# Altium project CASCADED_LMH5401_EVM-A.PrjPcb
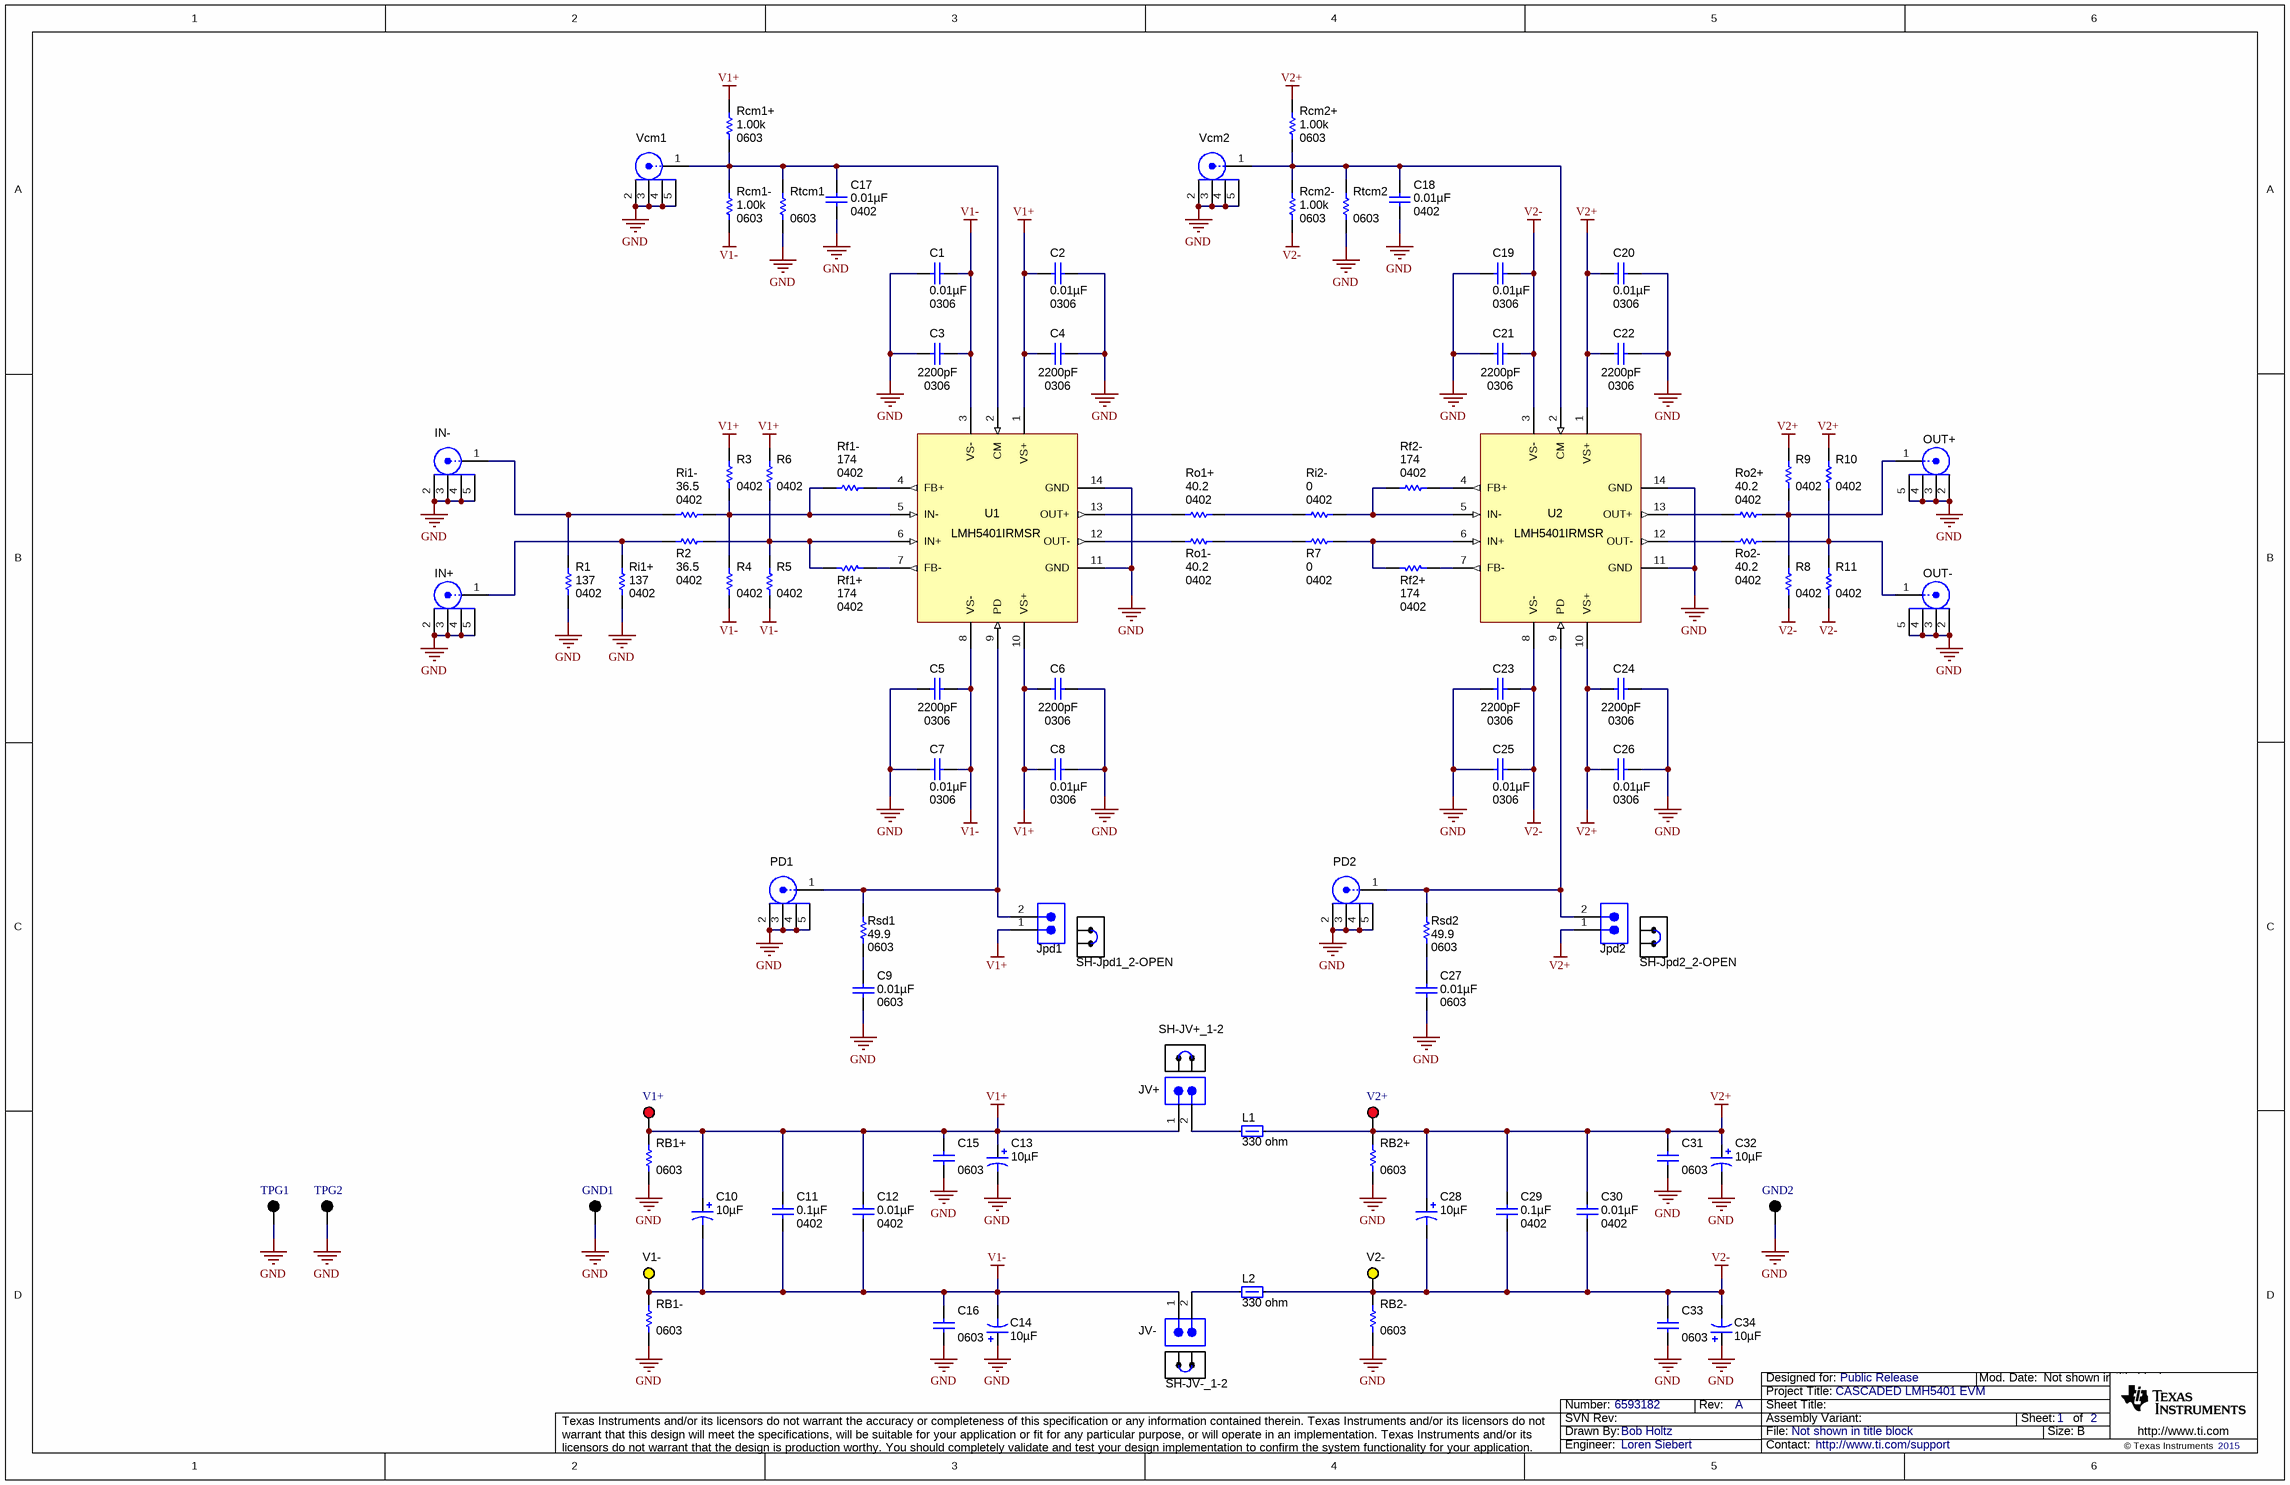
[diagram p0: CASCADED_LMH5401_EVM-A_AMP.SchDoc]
TechSupport: http://www.ti.com/support; SCH_Rev: A; PRJ_Title: CASCADED LMH5401 EVM; PRJ_Number: 6593182; PRJ_Engineer: Loren Siebert; PRJ_Customer: Public Release; PCB_Rev: A; PCB_Layout: Bob Holtz; CopyrightYear: 2015
2 sheets, 103 parts. Net scope: global (net labels, ports and power ports of the same name join across sheets).
Board file: CASCADED_LMH5401_EVM-A.PcbDoc
Sheets:
  CASCADED_LMH5401_EVM-A_AMP.SchDoc
  CASCADED_LMH5401_EVM-A_Hardware.SchDoc

## Sheet CASCADED_LMH5401_EVM-A_AMP.SchDoc
size 431 x 279 mm; Date: Not shown in title block; ApprovedBy: Not shown in title block; CheckedBy: Not shown in title block; Author: Not shown in title block; CompanyName: Not shown in title block; DrawnBy: Bob Holtz; Engineer: Not shown in title block; Organization: Not shown in title block; Address1: Not shown in title block; Address2: Not shown in title block; Address3: Not shown in title block; Address4: Not shown in title block; DocumentNumber: 1; Revision: Use project parameter SCH_Rev; SheetNumber: 1; SheetTotal: 2; PageSetup: Record=PageOptions¦CenterHorizontal=True¦CenterVertical=True¦PrintScale=0.62¦XCorrection=1.00¦YCorrection=1.00¦PrintKind=0¦BorderSize=5000000¦LeftOffset=0¦BottomOffset=0¦Orientation=2¦PaperLength=1000¦PaperWidth=1000¦Scale=100¦PaperSource=15¦PrintQuality=600¦MediaType=1¦DitherType=10¦PrintScaleMode=1¦PaperKind=Letter (8.5 x 11")¦PaperIndex=1

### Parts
C1  ValueDisplayed: 0.01µF  [0306]  (hidden comment: LLL185R71E103MA01L)
C2  ValueDisplayed: 0.01µF  [0306]  (hidden comment: LLL185R71E103MA01L)
C3  ValueDisplayed: 2200pF  [0306]  (hidden comment: LLL185R71H222MA01L)
C4  ValueDisplayed: 2200pF  [0306]  (hidden comment: LLL185R71H222MA01L)
C5  ValueDisplayed: 2200pF  [0306]  (hidden comment: LLL185R71H222MA01L)
C6  ValueDisplayed: 2200pF  [0306]  (hidden comment: LLL185R71H222MA01L)
C7  ValueDisplayed: 0.01µF  [0306]  (hidden comment: LLL185R71E103MA01L)
C8  ValueDisplayed: 0.01µF  [0306]  (hidden comment: LLL185R71E103MA01L)
C9  ValueDisplayed: 0.01µF  PackageReference: 0603  [0603L]  (hidden comment: GRM188R71C103KA01D)
C10  ValueDisplayed: 10µF  [3216-18]  (hidden comment: TPSA106K010R0900)
C11  ValueDisplayed: 0.1µF  PackageReference: 0402  [0402L]  (hidden comment: C1005X5R1A104K)
C12  ValueDisplayed: 0.01µF  PackageReference: 0402  [0402L]  (hidden comment: C1005X7R1E103K)
C13  ValueDisplayed: 10µF  [3216-18]  (hidden comment: TPSA106K010R0900)
C14  ValueDisplayed: 10µF  [3216-18]  (hidden comment: TPSA106K010R0900)
C15  PackageReference: 0603  [0603L]  (hidden comment: Used in BOM report)
C16  PackageReference: 0603  [0603L]  (hidden comment: Used in BOM report)
C17  ValueDisplayed: 0.01µF  PackageReference: 0402  [0402L]  (hidden comment: C1005X7R1E103K)
C18  ValueDisplayed: 0.01µF  PackageReference: 0402  [0402L]  (hidden comment: C1005X7R1E103K)
C19  ValueDisplayed: 0.01µF  [0306]  (hidden comment: LLL185R71E103MA01L)
C20  ValueDisplayed: 0.01µF  [0306]  (hidden comment: LLL185R71E103MA01L)
C21  ValueDisplayed: 2200pF  [0306]  (hidden comment: LLL185R71H222MA01L)
C22  ValueDisplayed: 2200pF  [0306]  (hidden comment: LLL185R71H222MA01L)
C23  ValueDisplayed: 2200pF  [0306]  (hidden comment: LLL185R71H222MA01L)
C24  ValueDisplayed: 2200pF  [0306]  (hidden comment: LLL185R71H222MA01L)
C25  ValueDisplayed: 0.01µF  [0306]  (hidden comment: LLL185R71E103MA01L)
C26  ValueDisplayed: 0.01µF  [0306]  (hidden comment: LLL185R71E103MA01L)
C27  ValueDisplayed: 0.01µF  PackageReference: 0603  [0603L]  (hidden comment: GRM188R71C103KA01D)
C28  ValueDisplayed: 10µF  [3216-18]  (hidden comment: TPSA106K010R0900)
C29  ValueDisplayed: 0.1µF  PackageReference: 0402  [0402L]  (hidden comment: C1005X5R1A104K)
C30  ValueDisplayed: 0.01µF  PackageReference: 0402  [0402L]  (hidden comment: C1005X7R1E103K)
C31  PackageReference: 0603  [0603L]  (hidden comment: Used in BOM report)
C32  ValueDisplayed: 10µF  [3216-18]  (hidden comment: TPSA106K010R0900)
C33  PackageReference: 0603  [0603L]  (hidden comment: Used in BOM report)
C34  ValueDisplayed: 10µF  [3216-18]  (hidden comment: TPSA106K010R0900)
GND1  5011  [Keystone5011]  (value not drawn)
GND2  5011  [Keystone5011]  (value not drawn)
IN+  142-0701-851  [Emerson_142-0701-851]  (value not drawn)
IN-  142-0701-851  [Emerson_142-0701-851]  (value not drawn)
Jpd1  TSW-102-07-G-S  [TSW-102-07-G-S]  (value not drawn)
Jpd2  TSW-102-07-G-S  [TSW-102-07-G-S]  (value not drawn)
JV+  TSW-102-07-G-S  [TSW-102-07-G-S]  (value not drawn)
JV-  TSW-102-07-G-S  [TSW-102-07-G-S]  (value not drawn)
L1  value 330 ohm  [0603L]  (hidden comment: BLM18SG331TN1D)
L2  value 330 ohm  [0603L]  (hidden comment: BLM18SG331TN1D)
OUT+  142-0701-851  [Emerson_142-0701-851]  (value not drawn)
OUT-  142-0701-851  [Emerson_142-0701-851]  (value not drawn)
PD1  142-0701-851  [Emerson_142-0701-851]  (value not drawn)
PD2  142-0701-851  [Emerson_142-0701-851]  (value not drawn)
R1  ValueDisplayed: 137  PackageReference: 0402  [0402L]  (hidden comment: CRCW0402137RFKED)
R2  ValueDisplayed: 36.5  PackageReference: 0402  [0402L]  (hidden comment: CRCW040236R5FKED)
R3  PackageReference: 0402  [0402L]  (hidden comment: Used in BOM report)
R4  PackageReference: 0402  [0402L]  (hidden comment: Used in BOM report)
R5  PackageReference: 0402  [0402L]  (hidden comment: Used in BOM report)
R6  PackageReference: 0402  [0402L]  (hidden comment: Used in BOM report)
R7  ValueDisplayed: 0  PackageReference: 0402  [0402L]  (hidden comment: CRCW04020000Z0ED)
R8  PackageReference: 0402  [0402L]  (hidden comment: Used in BOM report)
R9  PackageReference: 0402  [0402L]  (hidden comment: Used in BOM report)
R10  PackageReference: 0402  [0402L]  (hidden comment: Used in BOM report)
R11  PackageReference: 0402  [0402L]  (hidden comment: Used in BOM report)
RB1+  PackageReference: 0603  [0603L]  (hidden comment: Used in BOM report)
RB1-  PackageReference: 0603  [0603L]  (hidden comment: Used in BOM report)
RB2+  PackageReference: 0603  [0603L]  (hidden comment: Used in BOM report)
RB2-  PackageReference: 0603  [0603L]  (hidden comment: Used in BOM report)
Rcm1+  value 1.00k  PackageReference: 0603  [0603L]  (hidden comment: CRCW06031K00FKEA)
Rcm1-  value 1.00k  PackageReference: 0603  [0603L]  (hidden comment: CRCW06031K00FKEA)
Rcm2+  value 1.00k  PackageReference: 0603  [0603L]  (hidden comment: CRCW06031K00FKEA)
Rcm2-  value 1.00k  PackageReference: 0603  [0603L]  (hidden comment: CRCW06031K00FKEA)
Rf1+  ValueDisplayed: 174  PackageReference: 0402  [0402L]  (hidden comment: CRCW0402174RFKED)
Rf1-  ValueDisplayed: 174  PackageReference: 0402  [0402L]  (hidden comment: CRCW0402174RFKED)
Rf2+  ValueDisplayed: 174  PackageReference: 0402  [0402L]  (hidden comment: CRCW0402174RFKED)
Rf2-  ValueDisplayed: 174  PackageReference: 0402  [0402L]  (hidden comment: CRCW0402174RFKED)
Ri1+  ValueDisplayed: 137  PackageReference: 0402  [0402L]  (hidden comment: CRCW0402137RFKED)
Ri1-  ValueDisplayed: 36.5  PackageReference: 0402  [0402L]  (hidden comment: CRCW040236R5FKED)
Ri2-  ValueDisplayed: 0  PackageReference: 0402  [0402L]  (hidden comment: CRCW04020000Z0ED)
Ro1+  value 40.2  PackageReference: 0402  [0402L]  (hidden comment: CRCW040240R2FKED)
Ro1-  value 40.2  PackageReference: 0402  [0402L]  (hidden comment: CRCW040240R2FKED)
Ro2+  value 40.2  PackageReference: 0402  [0402L]  (hidden comment: CRCW040240R2FKED)
Ro2-  value 40.2  PackageReference: 0402  [0402L]  (hidden comment: CRCW040240R2FKED)
Rsd1  value 49.9  PackageReference: 0603  [0603L]  (hidden comment: CRCW060349R9FKEA)
Rsd2  value 49.9  PackageReference: 0603  [0603L]  (hidden comment: CRCW060349R9FKEA)
Rtcm1  PackageReference: 0603  [0603L]  (hidden comment: Used in BOM report)
Rtcm2  PackageReference: 0603  [0603L]  (hidden comment: Used in BOM report)
SH-Jpd1_2-OPEN  382811-6  (value not drawn)  (mechanical)
SH-Jpd2_2-OPEN  382811-6  (value not drawn)  (mechanical)
SH-JV+_1-2  382811-6  (value not drawn)  (mechanical)
SH-JV-_1-2  382811-6  (value not drawn)  (mechanical)
TPG1  5011  [Keystone5011]  (value not drawn)
TPG2  5011  [Keystone5011]  (value not drawn)
U1  LMH5401IRMSR  [RMS0014A]
U2  LMH5401IRMSR  [RMS0014A]
V1+  5010  [Keystone5010]  (value not drawn)
V1-  5014  [Keystone5014]  (value not drawn)
V2+  5010  [Keystone5010]  (value not drawn)
V2-  5014  [Keystone5014]  (value not drawn)
Vcm1  142-0701-851  [Emerson_142-0701-851]  (value not drawn)
Vcm2  142-0701-851  [Emerson_142-0701-851]  (value not drawn)

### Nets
GND: C1.1 C2.2 C3.2 C4.1 C5.2 C6.1 C7.1 C8.2 C9.2 C13.2(-) C14.1(+) C15.2 C16.2 C17.1 C18.1 C19.1 C20.2 C21.2 C22.1 C23.2 C24.1 C25.1 C26.2 C27.2 C31.2 C32.2(-) C33.2 C34.1(+) GND1.1 GND2.1 IN+.2 IN+.3 IN+.4 IN+.5 IN-.2 IN-.3 IN-.4 IN-.5 OUT+.2 OUT+.3 OUT+.4 OUT+.5 OUT-.2 OUT-.3 OUT-.4 OUT-.5 PD1.2 PD1.3 PD1.4 PD1.5 PD2.2 PD2.3 PD2.4 PD2.5 R1.1 RB1+.1 RB1-.2 RB2+.1 RB2-.2 Ri1+.1 Rtcm1.2 Rtcm2.2 TPG1.1 TPG2.1 U1.11(GND) U1.14(GND) U2.11(GND) U2.14(GND) Vcm1.2 Vcm1.3 Vcm1.4 Vcm1.5 Vcm2.2 Vcm2.3 Vcm2.4 Vcm2.5
V1+: C2.1 C4.2 C6.2 C8.1 C10.1(+) C11.2 C12.2 C13.1(+) C15.1 Jpd1.1 JV+.1 R3.2 R6.2 RB1+.2 Rcm1+.2 U1.1(VS+) U1.10(VS+) V1+.1
V1-: C1.2 C3.1 C5.1 C7.2 C10.2(-) C11.1 C12.1 C14.2(-) C16.1 JV-.1 R4.1 R5.1 RB1-.1 Rcm1-.1 U1.3(VS-) U1.8(VS-) V1-.1
V2+: C20.1 C22.2 C24.2 C26.1 C28.1(+) C29.2 C30.2 C31.1 C32.1(+) Jpd2.1 L1.2 R9.2 R10.2 RB2+.2 Rcm2+.2 U2.1(VS+) U2.10(VS+) V2+.1
V2-: C19.2 C21.1 C23.1 C25.2 C28.2(-) C29.1 C30.1 C33.1 C34.2(-) L2.2 R8.1 R11.1 RB2-.1 Rcm2-.1 U2.3(VS-) U2.8(VS-) V2-.1
NetC9_1: C9.1 Rsd1.1
NetC17_2: C17.2 Rcm1+.1 Rcm1-.2 Rtcm1.1 U1.2(CM) Vcm1.1
NetC18_2: C18.2 Rcm2+.1 Rcm2-.2 Rtcm2.1 U2.2(CM) Vcm2.1
NetC27_1: C27.1 Rsd2.1
NetIN+_1: IN+.1 R2.2 Ri1+.2
NetIN-_1: IN-.1 R1.2 Ri1-.1
NetJpd1_2: Jpd1.2 PD1.1 Rsd1.2 U1.9(PD)
NetJpd2_2: Jpd2.2 PD2.1 Rsd2.2 U2.9(PD)
NetJV+_2: JV+.2 L1.1
NetJV-_2: JV-.2 L2.1
NetOUT+_1: OUT+.1 R8.2 R9.1 Ro2+.2
NetOUT-_1: OUT-.1 R10.1 R11.2 Ro2-.2
NetR2_1: R2.1 R5.2 R6.1 Rf1+.2 U1.6(IN+)
NetR3_1: R3.1 R4.2 Rf1-.2 Ri1-.2 U1.5(IN-)
NetR7_1: R7.1 Rf2+.2 U2.6(IN+)
NetR7_2: R7.2 Ro1-.2
NetRf1+_1: Rf1+.1 U1.7(FB-)
NetRf1-_1: Rf1-.1 U1.4(FB+)
NetRf2+_1: Rf2+.1 U2.7(FB-)
NetRf2-_1: Rf2-.1 U2.4(FB+)
NetRf2-_2: Rf2-.2 Ri2-.2 U2.5(IN-)
NetRi2-_1: Ri2-.1 Ro1+.2
NetRo1+_1: Ro1+.1 U1.13(OUT+)
NetRo1-_1: Ro1-.1 U1.12(OUT-)
NetRo2+_1: Ro2+.1 U2.13(OUT+)
NetRo2-_1: Ro2-.1 U2.12(OUT-)

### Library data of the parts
C1 C2 C7 C8 C19 C20 C25 C26 = LLL185R71E103MA01L: CAP, CERM, 0.01uF, 25V, +/-20%, X7R, 0306; Manufacturer: MuRata; Polarized: N; CompType: Capacitor; U/M: EA; Cap_F: 0.00000001; Tolerance_%: 20; Value1: Unknown; VDC_V: 25; TaMin_C: -55; TaMax_C: 125
C3-C6 C21-C24 = LLL185R71H222MA01L: CAP, CERM, 2200pF, 50V, +/-20%, X7R, 0306; Manufacturer: MuRata; Polarized: N; CompType: Capacitor; U/M: EA; Cap_F: 0.0000000022; Tolerance_%: 20; Value1: Unknown; VDC_V: 50; TaMin_C: -55; TaMax_C: 125
C9 C27 = GRM188R71C103KA01D: CAP, CERM, 0.01uF, 16V, +/-10%, X7R, 0603; Manufacturer: MuRata; Polarized: N; CompType: Capacitor; U/M: EA; Cap_F: 0.00000001; Tolerance_%: 10; Value1: Unknown; VDC_V: 16; TaMin_C: -55; TaMax_C: 125
C10 C13 C14 C28 C32 C34 = TPSA106K010R0900: CAP, TA, 10uF, 10V, +/-10%, 0.9 ohm, SMD; Manufacturer: AVX; Polarized: Y; CompType: Capacitor; U/M: EA; Cap_F: 0.00001; Tolerance_%: 10; Value1: 0.9 ohm; ESR_Ohm: 0.9; IRMS_A: 0.26; TaMin_C: -55; TaMax_C: 125; Cap_Case: A
C11 C29 = C1005X5R1A104K: CAP, CERM, 0.1uF, 10V, +/-10%, X5R, 0402; Manufacturer: TDK; Polarized: N; CompType: Capacitor; U/M: EA; Cap_F: 0.0000001; Tolerance_%: 10; ESR_Ohm: 0.0186; Value1: 0.0186 ohm; TaMin_C: -55; TaMax_C: 85
C12 C17 C18 C30 = C1005X7R1E103K: CAP, CERM, 0.01uF, 25V, +/-10%, X7R, 0402; Manufacturer: TDK; ESR_Ohm: 0.0623; Polarized: N; TaMax_C: 125; TaMin_C: -55; Tolerance_%: 10; VDC_V: 25; Cap_F: 10.0E-9; CompType: Capacitor; Value1: 0.0623 ohm
C15 C16 C31 C33 = Capacitor: CAP, CERM, xxxF, xxV, [TempCo], xx%, [PackageReference]; Polarized: N; U/M: EA
GND1 GND2 TPG1 TPG2 = 5011: Test Point, TH, Multipurpose, Black; Manufacturer: Keystone Electronics; CompType: Test Point Loop
IN+ IN- OUT+ OUT- PD1 PD2 Vcm1 Vcm2 = 142-0701-851: Connector, SMT, End launch SMA 50 ohm; Manufacturer: Emerson Network Power; U/M: EA
Jpd1 Jpd2 JV+ JV- = TSW-102-07-G-S: Header, TH, 100mil, 2x1, Gold plated, 230 mil above insulator; Manufacturer: Samtec, Inc.; U/M: EA
L1 L2 = BLM18SG331TN1D: Ferrite Bead, 330 ohm @ 100 MHz, 1.5 A, 0603; Manufacturer: MuRata; Imax_A: 1.5; DCR_ohm: 0.07; Value1: 0.07 ohm; Value2: 1.5A; ZTyp@100MHz_Ohm: 330
R1 Ri1+ = CRCW0402137RFKED: RES, 137, 1%, 0.063 W, 0402; Manufacturer: Vishay-Dale; CompType: Resistor; Value: 137; Value_Code: 137R; Tolerance_%: 1; Power_W: 0.063; Value2: 0.063W; VDC_V: 50; TempCo: 100 ppm/C; EIA_Code: E96; U/M: EA
R2 Ri1- = CRCW040236R5FKED: RES, 36.5, 1%, 0.063 W, 0402; Manufacturer: Vishay-Dale; CompType: Resistor; Value: 36.5; Value_Code: 36R5; Tolerance_%: 1; Power_W: 0.063; Value2: 0.063W; VDC_V: 50; TempCo: 100 ppm/C; EIA_Code: E96; U/M: EA
R3-R6 R8-R11 RB1+ RB1- RB2+ RB2- Rtcm1 Rtcm2 = Resistor: RES, xxx ohm, x%, xW, [PackageReference]; U/M: EA
R7 Ri2- = CRCW04020000Z0ED: RES, 0, 5%, 0.063 W, 0402; Manufacturer: Vishay-Dale; CompType: Resistor; Value: 0; Value_Code: 0000; Tolerance_%: 5; Power_W: 0.063; Value2: 0.063W; VDC_V: 50; TempCo: 200 ppm/C; EIA_Code: E24; U/M: EA; AEC Category: Q200
Rcm1+ Rcm1- Rcm2+ Rcm2- = CRCW06031K00FKEA: RES, 1.00k ohm, 1%, 0.1W, 0603; Manufacturer: Vishay-Dale; CompType: Resistor; Res_ohm: 1000; Value_Code: 1k00; Tolerance_%: 1; Power_W: 0.1; VDC_V: 75; TempCo: 100 ppm/C; EIA_Code: E96; U/M: EA
Rf1+ Rf1- Rf2+ Rf2- = CRCW0402174RFKED: RES, 174, 1%, 0.063 W, 0402; Manufacturer: Vishay-Dale; CompType: Resistor; Value: 174; Value_Code: 174R; Tolerance_%: 1; Power_W: 0.063; Value2: 0.063W; VDC_V: 50; TempCo: 100 ppm/C; EIA_Code: E96; U/M: EA
Ro1+ Ro1- Ro2+ Ro2- = CRCW040240R2FKED: RES, 40.2 ohm, 1%, 0.063W, 0402; Manufacturer: Vishay-Dale; CompType: Resistor; Value_Code: 40R2; Tolerance_%: 1; Power_W: 0.063; VDC_V: 50; TempCo: 100 ppm/C; EIA_Code: E96; U/M: EA
Rsd1 Rsd2 = CRCW060349R9FKEA: RES, 49.9 ohm, 1%, 0.1W, 0603; Manufacturer: Vishay-Dale; CompType: Resistor; Value_Code: 49R9; Tolerance_%: 1; Power_W: 0.1; VDC_V: 75; TempCo: 100 ppm/C; EIA_Code: E96; U/M: EA
SH-Jpd1_2-OPEN SH-Jpd2_2-OPEN SH-JV+_1-2 SH-JV-_1-2 = 382811-6: Shunt, 100mil, Gold plated, Black; Manufacturer: AMP; Value: 1x2; Note: You can "mate" this to a header by matching the designator.  i.e. use SH-J3 for header J3
U1 U2 = LMH5401IRMSR: 8GHz Ultra Wideband Fully Differential Amplifier, RMS0014A; Alternate PartNumber: LMH5401IRMST; Manufacturer: Texas Instruments; SymbolCreator: Altium; CompType: IC; U/M: EA
V1+ V2+ = 5010: Test Point, TH, Multipurpose, Red; Manufacturer: Keystone Electronics; CompType: Test Point Loop
V1- V2- = 5014: Test Point, Multipurpose, Yellow, TH; Manufacturer: Keystone; CompType: Test Point Loop; U/M: EA

## Sheet CASCADED_LMH5401_EVM-A_Hardware.SchDoc
size 431 x 279 mm; Date: Not shown in title block; ApprovedBy: Not shown in title block; CheckedBy: Not shown in title block; Author: Not shown in title block; CompanyName: Not shown in title block; DrawnBy: Bob Holtz; Engineer: Not shown in title block; Organization: Not shown in title block; Address1: Not shown in title block; Address2: Not shown in title block; Address3: Not shown in title block; Address4: Not shown in title block; DocumentNumber: 2; Revision: Use project parameter SCH_Rev; SheetNumber: 2; SheetTotal: 2; PageSetup: Record=PageOptions¦CenterHorizontal=True¦CenterVertical=True¦PrintScale=1.00¦XCorrection=1.00¦YCorrection=1.00¦PrintKind=0¦BorderSize=5000000¦LeftOffset=0¦BottomOffset=0¦Orientation=2¦PaperLength=1000¦PaperWidth=1000¦Scale=100¦PaperSource=15¦PrintQuality=600¦MediaType=1¦DitherType=10¦PaperKind=Letter¦PrintScaleMode=1
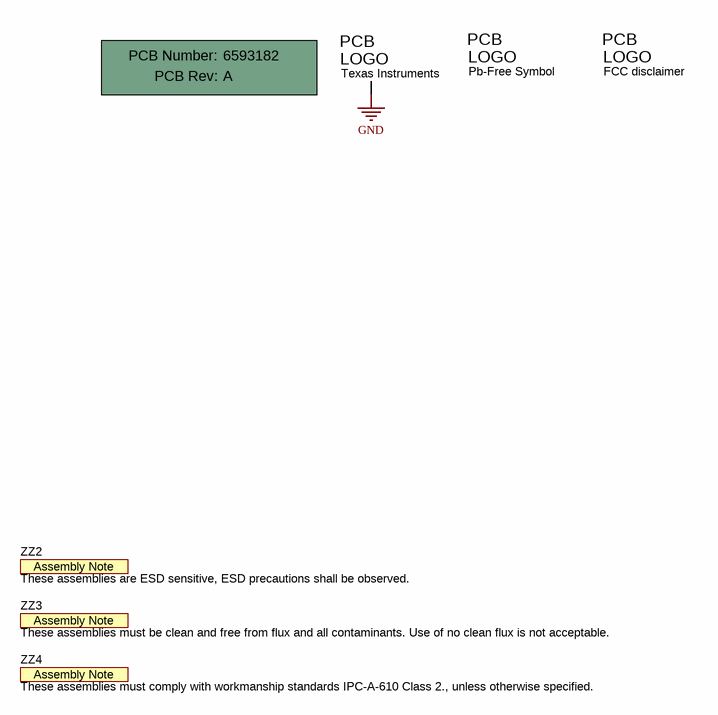
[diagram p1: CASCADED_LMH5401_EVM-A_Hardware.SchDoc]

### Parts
!PCB  Printed Circuit Board  (value not drawn)  (mechanical)
Logo1  Texas Instruments  [TI_Symbol_SolderMask_Small]  (no BOM)
Logo2  Pb-Free Symbol  [Pb-Free_Overlay_Small]  (no BOM)
Logo3  FCC disclaimer  [FCC_disclaimer]  (no BOM)
ZZ2  These assemblies are ESD sensitive, ESD precautions shall be observed.  [AssemblyNote]  (no BOM)
ZZ3  These assemblies must be clean and free from flux and all contaminants. Use of no clean flux is not acceptable.  [AssemblyNote]  (no BOM)
ZZ4  These assemblies must comply with workmanship standards IPC-A-610 Class 2., unless otherwise specified.  [AssemblyNote]  (no BOM)

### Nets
GND: Logo1.0

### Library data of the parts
!PCB = PCB: Manufacturer: Any; PartNumber: 6593182; SymbolCreator: a0412235
Logo1 = TI_Logo: Texas Instrument Corporate Signature; SymbolCreator: a0412235
Logo2 = Pb-Free: SymbolCreator: a0412235
Logo3 = FCC_disclaimer: SymbolCreator: codlsc
ZZ2-ZZ4 = AssemblyNote: SymbolCreator: codlsc

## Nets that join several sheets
GND: CASCADED_LMH5401_EVM-A_AMP (76 pins), CASCADED_LMH5401_EVM-A_Hardware (Logo1.0)

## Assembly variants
001: not fitted C15 C16 C31 C33 R3 R4 R5 R6 R8 R9 R10 R11 RB1+ RB1- RB2+ RB2- Rtcm1 Rtcm2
